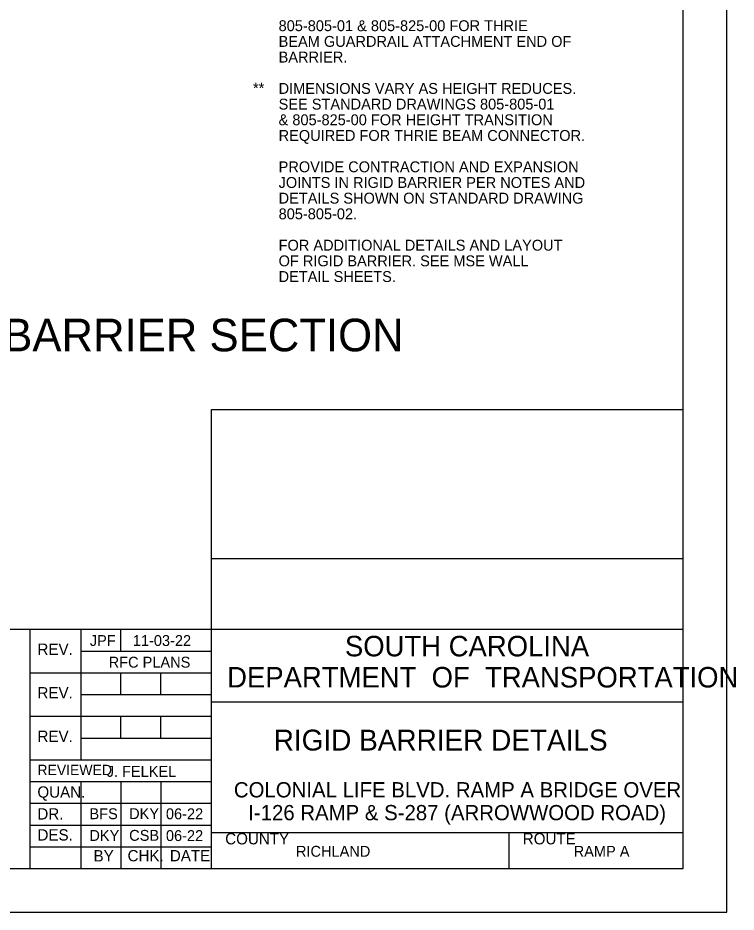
# Model space of a CAD drawing. Extents: x 96 to 240, y 601 to 689.
# Drawn here: x 207.27 to 240.27, y 601 to 642.1 of the extents above; entities that cross this region are included whole.
import ezdxf

# ---------------------------------------------------------------- set-up
doc = ezdxf.new("R2010")
doc.units = 0
for name, color, linetype in [('BR_AUTO DIMENSION', 7, 'Continuous'), ('BR_BORDER LINES', 7, 'Continuous'), ('BR_TEXT', 7, 'Continuous'), ('Level 31', 7, 'Continuous')]:
    doc.layers.add(name, color=color, linetype=linetype)

msp = doc.modelspace()

# ---------------------------------------------------------------- linework, layer by layer
at = {"layer": 'BR_BORDER LINES'}
for p, q in [((237.837, 603.003), (237.837, 687.003)), ((216.17, 603.003), (216.17, 624.11)), ((216.17, 624.11), (237.837, 624.11)), ((216.17, 617.251), (237.837, 617.251)), ((186.375, 614.004), (207.836, 614.004)), ((207.836, 603.003), (207.836, 614.004)), ((207.836, 614.004), (237.837, 614.004)), ((210.169, 614.004), (210.169, 608.004)), ((212.003, 613.004), (212.003, 614.004)), ((210.169, 613.004), (216.17, 613.004)), ((207.836, 612.004), (216.17, 612.004)), ((212.003, 611.004), (212.003, 612.004)), ((213.836, 611.004), (213.836, 612.004)), ((210.169, 611.004), (216.17, 611.004)), ((216.17, 610.67), (216.17, 610.67)), ((216.17, 610.67), (237.838, 610.67)), ((207.836, 610.004), (216.17, 610.004)), ((212.003, 609.004), (212.003, 610.004)), ((213.836, 609.004), (213.836, 610.004)), ((210.169, 609.004), (216.17, 609.004)), ((207.836, 608.004), (216.17, 608.004)), ((207.836, 607.004), (216.17, 607.004)), ((210.169, 607.004), (210.169, 603.003)), ((212.003, 607.004), (212.003, 603.003)), ((213.836, 607.004), (213.836, 603.003)), ((207.836, 606.004), (216.17, 606.004)), ((207.836, 605.004), (216.17, 605.004)), ((216.17, 604.67), (237.837, 604.67)), ((216.56, 604.67), (237.837, 604.67)), ((229.837, 603.003), (229.837, 604.67)), ((207.836, 604.003), (216.17, 604.003)), ((103.173, 603.003), (237.837, 603.003))]:
    msp.add_line(p, q, dxfattribs=at)
at = {"layer": 'Level 31'}
msp.add_line((227.004, 608.909), (227.004, 608.909), dxfattribs=at)
msp.add_lwpolyline([(95.84, 689.004), (95.84, 601.004), (239.84, 601.004), (239.84, 689.004)], dxfattribs=at)

# ---------------------------------------------------------------- texts
at = {"layer": 'BR_AUTO DIMENSION'}
for s, p in [('805-805-01 & 805-825-00 FOR THRIE', (219.251, 641.491)), ('BEAM GUARDRAIL ATTACHMENT END OF', (219.251, 640.77)), ('BARRIER.', (219.251, 640.05)), ('**', (218.075, 638.62)), ('DIMENSIONS VARY AS HEIGHT REDUCES.', (219.251, 638.609)), ('SEE STANDARD DRAWINGS 805-805-01', (219.251, 637.888)), ('& 805-825-00 FOR HEIGHT TRANSITION', (219.251, 637.168)), ('REQUIRED FOR THRIE BEAM CONNECTOR.', (219.251, 636.447)), ('PROVIDE CONTRACTION AND EXPANSION', (219.251, 635.006)), ('JOINTS IN RIGID BARRIER PER NOTES AND', (219.251, 634.286)), ('DETAILS SHOWN ON STANDARD DRAWING', (219.251, 633.566)), ('805-805-02.', (219.251, 632.845)), ('FOR ADDITIONAL DETAILS AND LAYOUT', (219.251, 631.404)), ('OF RIGID BARRIER. SEE MSE WALL', (219.251, 630.684)), ('DETAIL SHEETS.', (219.251, 629.963))]:
    msp.add_text(s, height=0.5, dxfattribs=at).set_placement(p)
at = {"layer": 'BR_TEXT'}
for s, height, p in [('CONCRETE RIGID BARRIER SECTION', 1.5, (188.661, 626.777)), ('JPF', 0.5, (210.578, 613.235)), ('11-03-22', 0.5, (212.554, 613.235)), ('SOUTH CAROLINA', 0.94348, (222.297, 612.757)), ('REV.', 0.52, (208.175, 612.825)), ('RFC PLANS', 0.5, (211.444, 612.24)), ('DEPARTMENT  OF  TRANSPORTATION', 0.94348, (216.886, 611.327)), ('REV.', 0.52, (208.175, 610.825)), ('REV.', 0.52, (208.175, 608.825)), ('RIGID BARRIER DETAILS', 0.96, (219.026, 608.429)), ('REVIEWED', 0.48, (208.172, 607.298)), ('J. FELKEL', 0.5, (211.352, 607.221)), ('QUAN.', 0.52, (208.17, 606.264)), ('COLONIAL LIFE BLVD. RAMP A BRIDGE OVER', 0.7, (217.196, 606.276)), ('DR.', 0.52, (208.17, 605.258)), ('06-22', 0.5, (214.075, 605.271)), ('I-126 RAMP & S-287 (ARROWWOOD ROAD)', 0.7, (217.854, 605.226)), ('DES.', 0.52, (208.175, 604.293)), ('06-22', 0.5, (214.075, 604.271)), ('COUNTY', 0.52, (216.798, 604.117)), ('ROUTE', 0.52, (230.466, 604.117)), ('BY', 0.52, (210.751, 603.331)), ('CHK.', 0.52, (212.314, 603.337)), ('DATE', 0.52, (214.255, 603.337)), ('RICHLAND', 0.5, (220.047, 603.549)), ('RAMP A', 0.5, (232.804, 603.549))]:
    msp.add_text(s, height=height, dxfattribs=at).set_placement(p)
for s, p in [('BFS', (210.562, 605.275)), ('DKY', (212.384, 605.281)), ('DKY', (210.558, 604.275)), ('CSB', (212.387, 604.281))]:
    msp.add_text(s, height=0.5, rotation=360, dxfattribs=at).set_placement(p)

doc.saveas('drawing.dxf')
